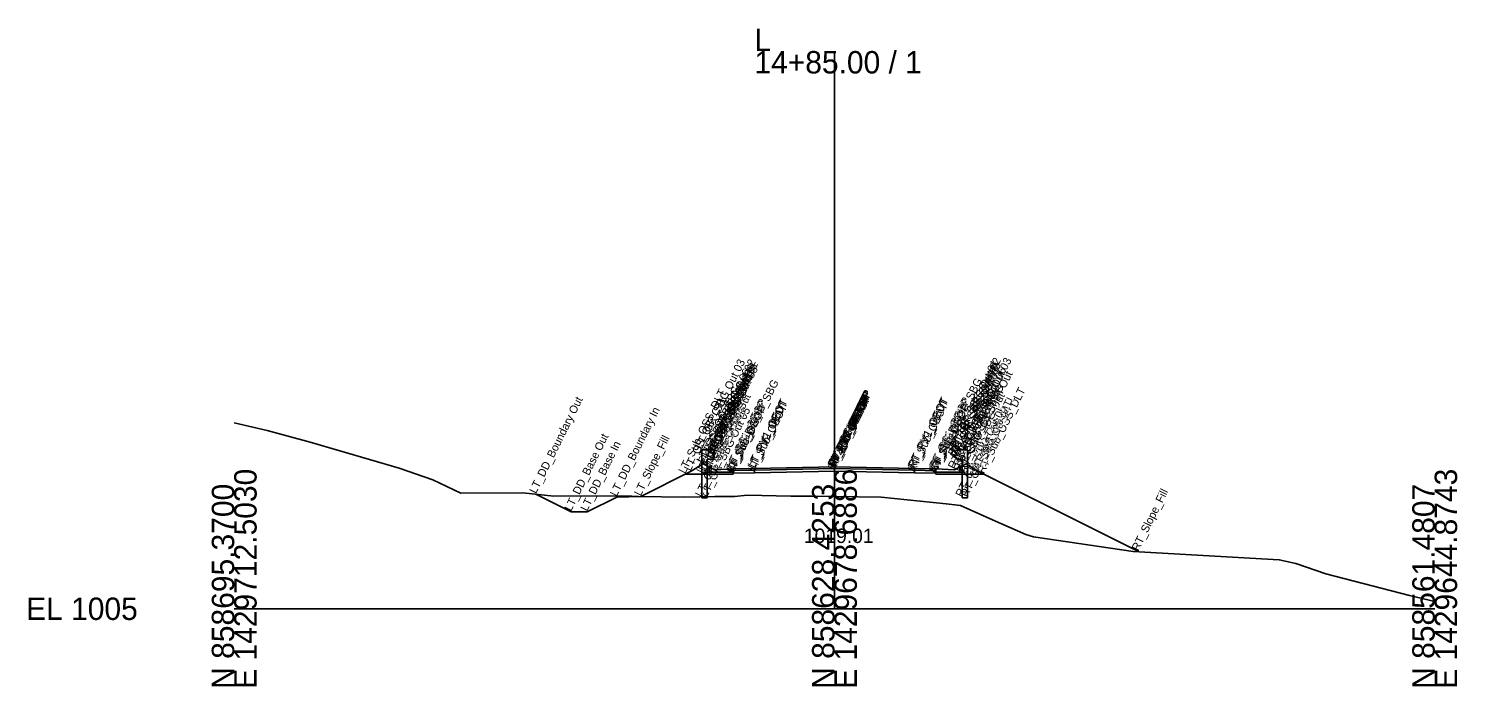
# Model space of a CAD drawing. Extents: x -26 to 2303, y -10 to 19558.
# Drawn here: x 2124.3 to 2302.8, y 990.3 to 1072.4 of the extents above; entities that cross this region are included whole.
import ezdxf

# ---------------------------------------------------------------- set-up
doc = ezdxf.new("R2010")
doc.units = 0
for name, color, linetype in [('Default', 7, 'Continuous'), ('Exist Cross Section Cell', 7, 'Continuous'), ('Exist XS Center Line Elevation Label', 7, 'Continuous'), ('Exist XS Ground Line', 7, 'Continuous'), ('Prop CMT Conc Surface', 7, 'Continuous'), ('Prop CMT Concrete Structures', 7, 'Continuous'), ('Prop CMT Ditch DDE', 7, 'Continuous'), ('Prop CMT Guardrail SBG', 7, 'Continuous'), ('Prop CMT Pvmt Course 1', 7, 'Continuous'), ('Prop CMT Pvmt Course 2', 7, 'Continuous'), ('Prop CMT Pvmt Course SBG', 7, 'Continuous'), ('Prop CMT Pvmt Surface', 7, 'Continuous'), ('Prop CMT Pvmt Surface Shoulder', 7, 'Continuous'), ('Prop CMT Shld Paved Course 1', 7, 'Continuous'), ('Prop CMT Shld Paved Course 2', 7, 'Continuous'), ('Prop CMT Slope Grass', 7, 'Continuous'), ('Prop CMT Subgrade Earthwork', 7, 'Continuous'), ('Prop XS Dump Level', 7, 'Continuous')]:
    doc.layers.add(name, color=color, linetype=linetype)

msp = doc.modelspace()

# ---------------------------------------------------------------- linework, layer by layer
at = {"layer": 'Exist Cross Section Cell'}
for p, q in [((2225, 1000), (2225, 1069.63)), ((2150, 1000), (2225, 1000)), ((2225, 1000), (2300, 1000))]:
    msp.add_line(p, q, dxfattribs=at)
at = {"layer": 'Exist XS Ground Line'}
msp.add_lwpolyline([(2150, 1023.21), (2154.11, 1022.24), (2159.51, 1020.79), (2170.62, 1017.57), (2174.83, 1016.11), (2178.32, 1014.45), (2186.07, 1014.47), (2189.93, 1014.07), (2198.35, 1014.08), (2199.67, 1014.06), (2199.98, 1014.03), (2200.52, 1014.01), (2206.31, 1013.92), (2210.05, 1014.01), (2212.54, 1014.01), (2214.09, 1014.2), (2219.54, 1014.07), (2222.16, 1014.05), (2225.15, 1014.01), (2230.84, 1013.93), (2238.96, 1013.11), (2240.77, 1012.91), (2244.75, 1011.1), (2248.93, 1009.29), (2249.88, 1009), (2262.33, 1007.17), (2280.57, 1006.12), (2282.64, 1005.65), (2286.41, 1004.36), (2296.86, 1001.66), (2300, 1000.89)], dxfattribs=at)
at = {"layer": 'Prop CMT Conc Surface'}
for points in [[(2212.35, 1017.45), (2210.02, 1017.36), (2209.35, 1017.7)], [(2237.68, 1017.45), (2240.01, 1017.36), (2240.68, 1017.7)]]:
    msp.add_lwpolyline(points, dxfattribs=at)
at = {"layer": 'Prop CMT Concrete Structures'}
for points in [[(2212.35, 1017.45), (2210.02, 1017.36), (2209.35, 1017.7)], [(2209.35, 1017.7), (2209.35, 1017.04)], [(2237.68, 1017.45), (2240.01, 1017.36), (2240.68, 1017.7)], [(2240.68, 1017.7), (2240.68, 1017.04)], [(2209.35, 1017.04), (2212.35, 1017.04)], [(2212.35, 1017.04), (2212.35, 1017.45)], [(2237.68, 1017.04), (2237.68, 1017.45)], [(2240.68, 1017.04), (2237.68, 1017.04)]]:
    msp.add_lwpolyline(points, dxfattribs=at)
at = {"layer": 'Prop CMT Ditch DDE'}
msp.add_lwpolyline([(2200.79, 1014.01), (2197.79, 1013.95), (2194.1, 1012.1), (2192.1, 1012.1), (2187.7, 1014.3)], dxfattribs=at)
at = {"layer": 'Prop CMT Guardrail SBG'}
for points in [[(2208.42, 1013.86), (2208.42, 1019.86)], [(2208.42, 1019.86), (2209.75, 1019.86), (2210.02, 1019.57)], [(2210.02, 1019.57), (2209.75, 1019.28)], [(2241.61, 1019.86), (2240.28, 1019.86), (2240.01, 1019.57)], [(2240.01, 1019.57), (2240.28, 1019.28)], [(2241.61, 1013.86), (2241.61, 1019.86)], [(2210.02, 1018.99), (2209.75, 1018.69), (2209.08, 1018.69)], [(2209.08, 1018.69), (2209.08, 1013.86)], [(2209.75, 1019.28), (2210.02, 1018.99)], [(2240.28, 1019.28), (2240.01, 1018.98)], [(2240.01, 1018.98), (2240.28, 1018.69), (2240.95, 1018.69)], [(2240.95, 1018.69), (2240.95, 1013.86)], [(2209.08, 1013.86), (2208.42, 1013.86)], [(2240.95, 1013.86), (2241.61, 1013.86)]]:
    msp.add_lwpolyline(points, dxfattribs=at)
at = {"layer": 'Prop CMT Pvmt Course 1'}
for points in [[(2225, 1017.71), (2215, 1017.51)], [(2225, 1017.5), (2225, 1017.71)], [(2225, 1017.71), (2235, 1017.51)], [(2225, 1017.5), (2225, 1017.71)], [(2215, 1017.51), (2215, 1017.3)], [(2215, 1017.3), (2225, 1017.5)], [(2235, 1017.3), (2225, 1017.5)], [(2235, 1017.51), (2235, 1017.3)]]:
    msp.add_lwpolyline(points, dxfattribs=at)
msp.add_lwpolyline([(2225, 1017.5), (2225, 1017.58), (2225, 1017.58), (2225, 1017.5)], close=True, dxfattribs=at)
msp.add_lwpolyline([(2225, 1017.5), (2225, 1017.58), (2225, 1017.58), (2225, 1017.5)], close=True, dxfattribs=at)
at = {"layer": 'Prop CMT Pvmt Course 2'}
for points in [[(2225, 1017.5), (2215, 1017.3)], [(2215, 1017.3), (2215, 1016.97)], [(2215, 1016.97), (2225, 1017.17)], [(2225, 1017.17), (2225, 1017.5)], [(2225, 1017.17), (2225, 1017.5)], [(2225, 1017.5), (2235, 1017.3)], [(2235, 1016.97), (2225, 1017.17)], [(2235, 1017.3), (2235, 1016.97)]]:
    msp.add_lwpolyline(points, dxfattribs=at)
at = {"layer": 'Prop CMT Pvmt Course SBG'}
for points in [[(2212.35, 1017.04), (2209.35, 1017.04), (2208.85, 1017.04), (2208.6, 1016.79)], [(2208.6, 1016.79), (2212.35, 1016.79)], [(2212.35, 1016.79), (2212.35, 1017.04)], [(2237.68, 1016.79), (2237.68, 1017.04)], [(2237.68, 1017.04), (2240.68, 1017.04), (2241.18, 1017.04), (2241.43, 1016.79)], [(2241.43, 1016.79), (2237.68, 1016.79)]]:
    msp.add_lwpolyline(points, dxfattribs=at)
at = {"layer": 'Prop CMT Pvmt Surface'}
for points in [[(2225, 1017.71), (2215, 1017.51)], [(2225, 1017.71), (2235, 1017.51)]]:
    msp.add_lwpolyline(points, dxfattribs=at)
at = {"layer": 'Prop CMT Pvmt Surface Shoulder'}
for points in [[(2215, 1017.51), (2212.35, 1017.45)], [(2235, 1017.51), (2237.68, 1017.45)]]:
    msp.add_lwpolyline(points, dxfattribs=at)
at = {"layer": 'Prop CMT Shld Paved Course 1'}
for points in [[(2215, 1017.51), (2212.35, 1017.45)], [(2212.35, 1017.45), (2212.35, 1017.25)], [(2212.35, 1017.25), (2215, 1017.3)], [(2215, 1017.3), (2215, 1017.51)], [(2235, 1017.51), (2237.68, 1017.45)], [(2235, 1017.3), (2235, 1017.51)], [(2237.68, 1017.24), (2235, 1017.3)], [(2237.68, 1017.45), (2237.68, 1017.24)]]:
    msp.add_lwpolyline(points, dxfattribs=at)
at = {"layer": 'Prop CMT Shld Paved Course 2'}
for points in [[(2215, 1017.3), (2212.35, 1017.25)], [(2212.35, 1017.25), (2212.35, 1017.04), (2212.35, 1016.91)], [(2212.35, 1016.91), (2215, 1016.97)], [(2215, 1016.97), (2215, 1017.3)], [(2235, 1017.3), (2237.68, 1017.24)], [(2235, 1016.97), (2235, 1017.3)], [(2237.68, 1016.91), (2235, 1016.97)], [(2237.68, 1017.24), (2237.68, 1017.04), (2237.68, 1016.91)]]:
    msp.add_lwpolyline(points, dxfattribs=at)
at = {"layer": 'Prop CMT Slope Grass'}
for points in [[(2209.35, 1017.7), (2208.58, 1018.1), (2207.02, 1017.12), (2200.79, 1014.01)], [(2240.68, 1017.7), (2241.45, 1018.1), (2243.01, 1017.12), (2262.98, 1007.14)]]:
    msp.add_lwpolyline(points, dxfattribs=at)
at = {"layer": 'Prop CMT Subgrade Earthwork'}
for points in [[(2212.35, 1016.79), (2208.6, 1016.79), (2206.35, 1016.79)], [(2215, 1016.97), (2212.35, 1016.91)], [(2212.35, 1016.91), (2212.35, 1016.79)], [(2225, 1017.17), (2215, 1016.97)], [(2225, 1017.17), (2235, 1016.97)], [(2235, 1016.97), (2237.68, 1016.91)], [(2237.68, 1016.91), (2237.68, 1016.79)], [(2237.68, 1016.79), (2241.43, 1016.79), (2243.68, 1016.79)]]:
    msp.add_lwpolyline(points, dxfattribs=at)

# ---------------------------------------------------------------- texts
at = {"layer": 'Default'}
msp.add_text('-', height=0.0001, dxfattribs=at).set_placement((2150, 1000))
at = {"layer": 'Exist Cross Section Cell'}
for s, p in [('L', (2215, 1069.63)), ('14+85.00 / 1', (2215, 1066.83)), ('EL 1005', (2124, 998.6))]:
    msp.add_text(s, height=2.8, dxfattribs=at).set_placement(p)
for s, p in [('E 1429712.5030', (2152.8, 990)), ('E 1429678.6886', (2227.8, 990)), ('E 1429644.8743', (2302.8, 990)), ('N 858695.3700', (2150, 990)), ('N 858628.4253', (2225, 990)), ('N 858561.4807', (2300, 990))]:
    msp.add_text(s, height=2.8, rotation=90, dxfattribs=at).set_placement(p)
at = {"layer": 'Exist XS Center Line Elevation Label'}
msp.add_text('1019.01', height=1.8, dxfattribs=at).set_placement((2221.19, 1008.21))
at = {"layer": 'Prop XS Dump Level'}
for s, p in [('LT_GR_SBG Out 03', (2208.42, 1019.86)), ('LT_GR_SBG Out 02', (2209.75, 1019.86)), ('LT_GR_SBG Out 09', (2209.75, 1019.28)), ('LT_GR_SBG Out 01', (2210.02, 1019.57)), ('LT_GR_SBG Out 08', (2210.02, 1018.99)), ('RT_GR_SBG Out 01', (2240.01, 1019.57)), ('RT_GR_SBG Out 08', (2240.01, 1018.98)), ('RT_GR_SBG Out 02', (2240.28, 1019.86)), ('RT_GR_SBG Out 09', (2240.28, 1019.28)), ('RT_GR_SBG Out 07', (2240.28, 1018.69)), ('RT_GR_SBG Out 06', (2240.95, 1018.69)), ('RT_GR_SBG Out 03', (2241.61, 1019.86)), ('LT_SBG_C1 Shelf Out', (2208.85, 1017.04)), ('LT_GR_SBG Out 06', (2209.08, 1018.69)), ('LT_GR_SBG Out 07', (2209.75, 1018.69)), ('LT_Sub_OEOP_SBG', (2212.35, 1016.79)), ('RT_Sub_OEOP_SBG', (2237.68, 1016.79)), ('RT_SBG_C1 Shelf Out', (2241.18, 1017.04)), ('LT_Sub_OSS_DLT', (2206.35, 1016.79)), ('LT_GS_OS_SBG', (2208.58, 1018.1)), ('LT_Sub_SBG Out', (2208.6, 1016.79)), ('LT_CG_Top_BOC', (2209.35, 1017.7)), ('LT_CG_Bot_BOC', (2209.35, 1017.04)), ('LT_CG_Top_Gut', (2210.02, 1017.36)), ('RT_PV1_OEEOP', (2225, 1017.58)), ('RT_PV2_OEEOP', (2225, 1017.5)), ('LT_PV1_OEEOP', (2225, 1017.58)), ('LT_PV2_OEEOP', (2225, 1017.5)), ('RT_Sub_OEEOP', (2225, 1017.17)), ('RT_PV1_IEEOP', (2225, 1017.58)), ('RT_PV2_IEEOP', (2225, 1017.5)), ('LT_Sub_OEEOP', (2225, 1017.17)), ('RT_CG_Top_Gut', (2240.01, 1017.36)), ('RT_CG_Top_BOC', (2240.68, 1017.7)), ('RT_CG_Bot_BOC', (2240.68, 1017.04)), ('RT_Sub_SBG Out', (2241.43, 1016.79)), ('RT_GS_OS_SBG', (2241.45, 1018.1)), ('RT_Sub_OSS_DLT', (2243.68, 1016.79)), ('LT_DD_Boundary Out', (2187.7, 1014.3)), ('LT_DD_Boundary In', (2197.79, 1013.95)), ('LT_GS_OS_CTL', (2207.02, 1017.12)), ('LT_GR_SBG Out 04', (2208.42, 1013.86)), ('LT_GR_SBG Out 05', (2209.08, 1013.86)), ('LT_PS1_OEOP', (2212.35, 1017.45)), ('LT_PS2_OEOP', (2212.35, 1017.25)), ('LT_Sub_OEOP', (2212.35, 1016.91)), ('LT_CG_Bot_IE', (2212.35, 1017.04)), ('LT_PV1_OEOT', (2215, 1017.51)), ('LT_PV2_OEOT', (2215, 1017.3)), ('LT_Sub_OEOT', (2215, 1016.97)), ('LT_PV1_IEEOP', (2225, 1017.58)), ('LT_PV2_IEEOP', (2225, 1017.5)), ('RT_PV1_OEOT', (2235, 1017.51)), ('RT_PV2_OEOT', (2235, 1017.3)), ('RT_Sub_OEOT', (2235, 1016.97)), ('RT_PS1_OEOP', (2237.68, 1017.45)), ('RT_PS2_OEOP', (2237.68, 1017.24)), ('RT_Sub_OEOP', (2237.68, 1016.91)), ('RT_CG_Bot_IE', (2237.68, 1017.04)), ('RT_GR_SBG Out 05', (2240.95, 1013.86)), ('RT_GR_SBG Out 04', (2241.61, 1013.86)), ('RT_GS_OS_CTL', (2243.01, 1017.12)), ('PV1_PGL', (2225, 1017.71)), ('LT_DD_Base Out', (2192.1, 1012.1)), ('LT_Slope_Fill', (2200.79, 1014.01)), ('PV2_PGL', (2225, 1017.5)), ('LT_DD_Base In', (2194.1, 1012.1)), ('RT_Slope_Fill', (2262.98, 1007.14))]:
    msp.add_text(s, height=1, rotation=63.5833, dxfattribs=at).set_placement(p)

doc.saveas('drawing.dxf')
